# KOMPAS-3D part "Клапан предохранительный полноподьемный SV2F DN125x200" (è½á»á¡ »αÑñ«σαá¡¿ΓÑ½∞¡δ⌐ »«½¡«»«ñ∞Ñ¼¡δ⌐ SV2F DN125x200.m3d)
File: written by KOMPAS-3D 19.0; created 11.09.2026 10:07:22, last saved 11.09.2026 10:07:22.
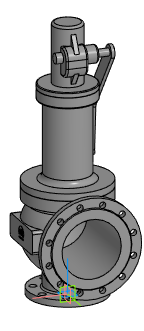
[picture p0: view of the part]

Document properties: Автор: Энергия; Полное имя файла: Z:\3.Личные\sachek\Dendor\_3D для проектировщиков\5.9 SV2F. Клапан предохранительный полноподьемный\SV2F_STP\Клапан предохранительный полноподьемный SV2F DN125x200.m3d

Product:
- Part/product: Клапан предохранительный полноподьемный SV2F DN125x200

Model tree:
1. Операция без истории:1  (labels: Клапан предохранительный полноподьемный SV2F DN125x200)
